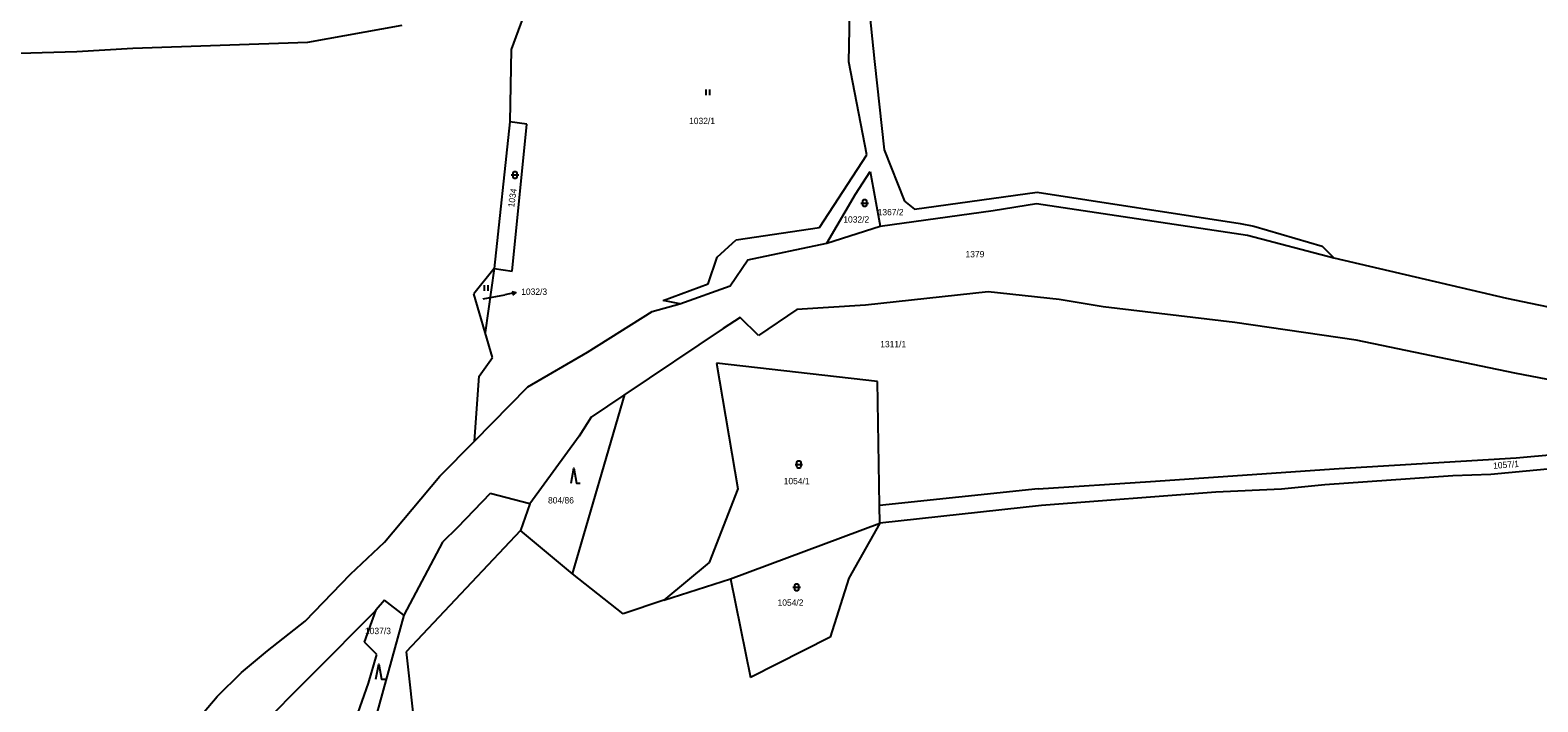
# Model space of a CAD drawing. Extents: x -845995 to -842497, y -1063614 to -1059680.
# Drawn here: x -843977.7 to -843573.2, y -1061386 to -1061205.9 of the extents above; entities that cross this region are included whole.
import ezdxf

# ---------------------------------------------------------------- set-up
doc = ezdxf.new("R2010")
doc.units = 0
for name, color, linetype in [('KN_HRANICE', 7, 'Continuous'), ('KN_KULTURY', 7, 'Continuous'), ('KN_PARCELY', 7, 'Continuous')]:
    doc.layers.add(name, color=color, linetype=linetype)

# ---------------------------------------------------------------- blocks, each defined once
blk = doc.blocks.new('306')
for p, q in [((-0.5, 1.5), (-0.5, 0)), ((0.5, 0), (0.5, 1.5))]:
    blk.add_line(p, q)
blk = doc.blocks.new('308')
blk.add_lwpolyline([(-0.75, 0), (0, 4), (0.75, 0), (1.75, 0)])
blk = doc.blocks.new('316')
for points in [[(-1, 1), (0.27, 1), (1, 1)], [(-0.5, 1.5), (-0.4, 1.79), (-0.15, 1.97), (0.16, 1.97), (0.41, 1.79), (0.51, 1.5), (0.51, 0.5), (0.41, 0.21), (0.16, 0.03), (-0.15, 0.03), (-0.4, 0.21), (-0.5, 0.5), (-0.5, 1.5)]]:
    blk.add_lwpolyline(points)
blk = doc.blocks.new('10292')
blk.add_line((0, 3), (0, 0))
blk.add_lwpolyline([(-0.5, 2), (0, 3), (0.5, 2)])

msp = doc.modelspace()

# ---------------------------------------------------------------- linework, layer by layer
at = {"layer": 'KN_HRANICE'}
for p, q in [((-843758.11, -1061214.34), (-843757.44, -1061183.54)), ((-843842.44, -1061194.12), (-843848.69, -1061211.1)), ((-843752.83, -1061198.6), (-843751.24, -1061214.26)), ((-843878, -1061204.64), (-843903.31, -1061209.15)), ((-843965.16, -1061211.72), (-844011.33, -1061212.96)), ((-843950.16, -1061210.8), (-843965.16, -1061211.72)), ((-843903.31, -1061209.15), (-843950.16, -1061210.8)), ((-843848.69, -1061211.1), (-843848.99, -1061230.47)), ((-843753.24, -1061239.32), (-843758.11, -1061214.34)), ((-843751.24, -1061214.26), (-843748.59, -1061237.93)), ((-843848.99, -1061230.47), (-843853.2, -1061269.79)), ((-843844.45, -1061231.05), (-843848.99, -1061230.47)), ((-843848.42, -1061270.5), (-843844.45, -1061231.05)), ((-843765.97, -1061258.82), (-843753.24, -1061239.32)), ((-843748.59, -1061237.93), (-843743.16, -1061251.77)), ((-843756.33, -1061249.86), (-843752.32, -1061243.82)), ((-843752.32, -1061243.82), (-843749.69, -1061258.46)), ((-843763.99, -1061263.04), (-843756.33, -1061249.86)), ((-843743.16, -1061251.77), (-843740.51, -1061253.88)), ((-843740.51, -1061253.88), (-843707.55, -1061249.34)), ((-843719.38, -1061254.23), (-843707.71, -1061252.4)), ((-843707.71, -1061252.4), (-843651.14, -1061260.86)), ((-843707.55, -1061249.34), (-843653.11, -1061257.75)), ((-843749.69, -1061258.46), (-843719.38, -1061254.23)), ((-843788.34, -1061262.14), (-843765.97, -1061258.82)), ((-843763.99, -1061263.04), (-843749.69, -1061258.46)), ((-843653.11, -1061257.75), (-843649.46, -1061258.41)), ((-843649.46, -1061258.41), (-843631.1, -1061263.83)), ((-843793.44, -1061266.79), (-843788.34, -1061262.14)), ((-843785.22, -1061267.47), (-843763.99, -1061263.04)), ((-843651.14, -1061260.86), (-843627.97, -1061266.91)), ((-843631.1, -1061263.83), (-843627.97, -1061266.91)), ((-843795.86, -1061273.88), (-843793.44, -1061266.79)), ((-843789.91, -1061274.45), (-843785.22, -1061267.47)), ((-843627.97, -1061266.91), (-843581.64, -1061277.78)), ((-843853.2, -1061269.79), (-843858.65, -1061276.59)), ((-843853.2, -1061269.79), (-843855.66, -1061286.98)), ((-843853.2, -1061269.79), (-843848.42, -1061270.5)), ((-843855.66, -1061286.98), (-843858.65, -1061276.59)), ((-843807.87, -1061278.34), (-843795.86, -1061273.88)), ((-843803.41, -1061279.25), (-843789.91, -1061274.45)), ((-843720.66, -1061276.06), (-843753.6, -1061279.61)), ((-843701.61, -1061278.11), (-843720.66, -1061276.06)), ((-843810.84, -1061281.31), (-843803.41, -1061279.25)), ((-843803.41, -1061279.25), (-843807.87, -1061278.34)), ((-843772.02, -1061280.75), (-843782.31, -1061287.73)), ((-843753.6, -1061279.61), (-843772.02, -1061280.75)), ((-843689.83, -1061280.06), (-843701.61, -1061278.11)), ((-843654.49, -1061284.29), (-843689.83, -1061280.06)), ((-843581.64, -1061277.78), (-843550.13, -1061284.28)), ((-843828.23, -1061292.19), (-843810.84, -1061281.31)), ((-843787.23, -1061282.93), (-843791.76, -1061285.89)), ((-843782.31, -1061287.73), (-843787.23, -1061282.93)), ((-843621.95, -1061288.97), (-843654.49, -1061284.29)), ((-843853.72, -1061293.7), (-843855.66, -1061286.98)), ((-843791.76, -1061285.89), (-843818.17, -1061303.58)), ((-843844.22, -1061301.54), (-843828.23, -1061292.19)), ((-843579.4, -1061297.9), (-843621.95, -1061288.97)), ((-843857.29, -1061298.68), (-843853.72, -1061293.7)), ((-843750.4, -1061300.1), (-843793.61, -1061295.15)), ((-843793.61, -1061295.15), (-843787.86, -1061328.87)), ((-843858.52, -1061316.07), (-843857.29, -1061298.68)), ((-843749.88, -1061333.37), (-843750.4, -1061300.1)), ((-843562.17, -1061301.21), (-843579.4, -1061297.9)), ((-843858.52, -1061316.07), (-843844.22, -1061301.54)), ((-843832.24, -1061351.7), (-843818.17, -1061303.58)), ((-843818.41, -1061303.74), (-843827.22, -1061309.69)), ((-843818.17, -1061303.58), (-843818.41, -1061303.74)), ((-843827.22, -1061309.69), (-843830.42, -1061314.73)), ((-843867.78, -1061325.46), (-843858.52, -1061316.07)), ((-843830.42, -1061314.73), (-843843.69, -1061332.92)), ((-843626.56, -1061323.43), (-843579.08, -1061320.55)), ((-843579.08, -1061320.55), (-843568.11, -1061319.58)), ((-843677.18, -1061326.93), (-843626.56, -1061323.43)), ((-843585.86, -1061325.04), (-843596.03, -1061325.37)), ((-843552.81, -1061321.96), (-843585.86, -1061325.04)), ((-843882.65, -1061343.2), (-843867.78, -1061325.46)), ((-843787.86, -1061328.87), (-843795.52, -1061348.6)), ((-843707.33, -1061328.88), (-843749.88, -1061333.37)), ((-843707.33, -1061328.88), (-843677.18, -1061326.93)), ((-843641.98, -1061328.96), (-843659.64, -1061329.79)), ((-843630.42, -1061327.79), (-843641.98, -1061328.96)), ((-843596.03, -1061325.37), (-843630.42, -1061327.79)), ((-843854.29, -1061330.11), (-843863.1, -1061339.26)), ((-843843.69, -1061332.92), (-843854.29, -1061330.11)), ((-843843.69, -1061332.92), (-843846.21, -1061340.02)), ((-843659.64, -1061329.79), (-843706.37, -1061333.38)), ((-843749.81, -1061338.04), (-843749.88, -1061333.37)), ((-843706.37, -1061333.38), (-843749.81, -1061338.04)), ((-843846.21, -1061340.02), (-843876.82, -1061372.57)), ((-843863.1, -1061339.26), (-843867.1, -1061343.15)), ((-843832.24, -1061351.7), (-843846.21, -1061340.02)), ((-843789.86, -1061352.99), (-843749.81, -1061338.04)), ((-843749.81, -1061338.04), (-843758.11, -1061352.86)), ((-843891.79, -1061351.74), (-843882.65, -1061343.2)), ((-843867.1, -1061343.15), (-843877.51, -1061362.72)), ((-843795.52, -1061348.6), (-843807.69, -1061358.77)), ((-843903.92, -1061364.33), (-843891.79, -1061351.74)), ((-843818.66, -1061362.35), (-843832.24, -1061351.7)), ((-843807.69, -1061358.77), (-843789.86, -1061352.99)), ((-843789.86, -1061352.99), (-843784.44, -1061379.49)), ((-843758.11, -1061352.86), (-843763.06, -1061368.65)), ((-843887.98, -1061370.03), (-843884.91, -1061361.32)), ((-843884.91, -1061361.32), (-843885.63, -1061362.15)), ((-843882.66, -1061358.72), (-843884.91, -1061361.32)), ((-843877.51, -1061362.72), (-843882.66, -1061358.72)), ((-843807.69, -1061358.77), (-843818.66, -1061362.35)), ((-843885.63, -1061362.15), (-843917.63, -1061394.28)), ((-843914.06, -1061372.28), (-843903.92, -1061364.33)), ((-843877.51, -1061362.72), (-843889.86, -1061407.89)), ((-843763.06, -1061368.65), (-843784.44, -1061379.49)), ((-843921.04, -1061378.12), (-843914.06, -1061372.28)), ((-843884.73, -1061373.28), (-843887.98, -1061370.03)), ((-843886.98, -1061381.02), (-843884.73, -1061373.28)), ((-843876.82, -1061372.57), (-843870.39, -1061430.31)), ((-843927.56, -1061384.52), (-843921.04, -1061378.12)), ((-843890.35, -1061390.64), (-843886.98, -1061381.02)), ((-843945.96, -1061406.23), (-843927.56, -1061384.52))]:
    msp.add_line(p, q, dxfattribs=at)
at = {"layer": 'KN_PARCELY'}
msp.add_line((-843856.19, -1061277.9), (-843850.36, -1061276.81), dxfattribs=at)

# ---------------------------------------------------------------- block references
at = {"layer": 'KN_KULTURY'}
for name, p in [('306', (-843795.91, -1061223.31)), ('316', (-843847.66, -1061245.71)), ('316', (-843753.83, -1061253.23)), ('306', (-843855.38, -1061275.76)), ('308', (-843831.87, -1061327.35)), ('316', (-843771.5, -1061323.33)), ('316', (-843772.08, -1061356.28)), ('308', (-843884.21, -1061379.89))]:
    msp.add_blockref(name, p, dxfattribs=at)
at = {"layer": 'KN_PARCELY', "rotation": -79.42256800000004}
msp.add_blockref('10292', (-843850.36, -1061276.81), dxfattribs=at)

# ---------------------------------------------------------------- texts
at = {"layer": 'KN_PARCELY'}
for s, height, p in [('1032/1', 1.7, (-843800.94, -1061231.07)), ('1032/2', 1.7, (-843759.57, -1061257.48)), ('1367/2', 1.7, (-843750.35, -1061255.54)), ('1379', 1.7, (-843726.78, -1061266.8)), ('1032/3', 1.7, (-843845.98, -1061276.86)), ('1032/3', 0.1, (-843856.49, -1061277.9)), ('1311/1', 1.7, (-843749.66, -1061290.91)), ('1054/1', 1.7, (-843775.56, -1061327.64)), ('804/86', 1.7, (-843838.79, -1061332.8)), ('1054/2', 1.7, (-843777.21, -1061360.24)), ('1037/3', 1.7, (-843887.89, -1061367.84))]:
    msp.add_text(s, height=height, dxfattribs=at).set_placement(p)
for s, rotation, p in [('1034', 81.933, (-843847.87, -1061253.49)), ('1057/1', 4.412, (-843585.17, -1061323.54))]:
    msp.add_text(s, height=1.7, rotation=rotation, dxfattribs=at).set_placement(p)

doc.saveas('drawing.dxf')
